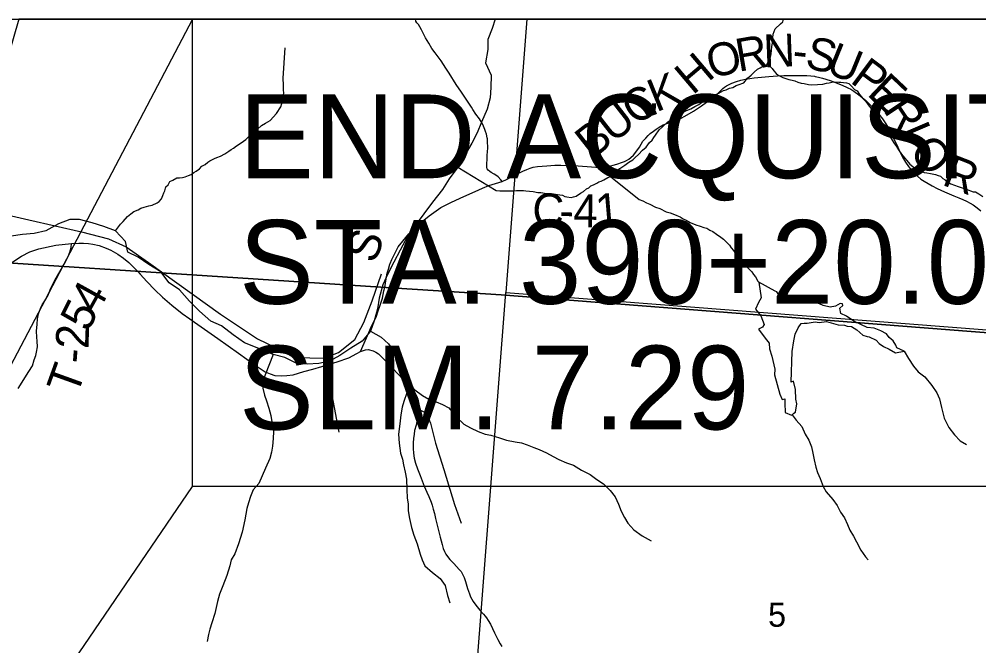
# Model space of a CAD drawing. Extents: x 0 to 34, y 0 to 22.
# Drawn here: x 6.769 to 8.431, y 19.816 to 20.9 of the extents above; entities that cross this region are included whole.
import ezdxf

# ---------------------------------------------------------------- set-up
doc = ezdxf.new("R2010")
doc.units = 0
for name, color, linetype in [('GM_X_County_Road', 7, 'Continuous'), ('GM_X_County_Road_Text', 7, 'Continuous'), ('GM_X_Minor_Lake', 7, 'Continuous'), ('GM_X_Minor_River', 7, 'Continuous'), ('GM_X_Rail_Line', 7, 'Continuous'), ('GM_X_Section', 7, 'Continuous'), ('GM_X_Section_Text', 7, 'Continuous'), ('GM_X_State_Route', 7, 'Continuous'), ('GM_X_Township_Road', 7, 'Continuous'), ('GM_X_Township_Road_Text', 7, 'Continuous'), ('GM_X_Unincorporated', 7, 'Continuous'), ('SH_Cut_Line', 7, 'Continuous'), ('SH_Data', 7, 'Continuous'), ('SH_Masking', 7, 'Continuous'), ('SH_Text', 7, 'Continuous')]:
    doc.layers.add(name, color=color, linetype=linetype)

msp = doc.modelspace()

# ---------------------------------------------------------------- linework, layer by layer
at = {"layer": 'GM_X_County_Road'}
for points in [[(7.5391, 20.593), (7.5586, 20.6019), (7.5715, 20.6074), (7.5825, 20.6121), (7.6053, 20.619), (7.614, 20.6232), (7.6228, 20.6278), (7.6294, 20.6313), (7.6364, 20.6349), (7.6412, 20.6372), (7.648, 20.64), (7.6537, 20.6422), (7.6589, 20.6436), (7.6664, 20.6448), (7.6828, 20.646), (7.6968, 20.6472), (7.7073, 20.6474), (7.7212, 20.6468), (7.7373, 20.6464), (7.76, 20.6443), (7.7677, 20.6436), (7.7731, 20.6435), (7.7789, 20.6437), (7.7848, 20.6442), (7.791, 20.6455), (7.7978, 20.6474), (7.8039, 20.6492), (7.8139, 20.6527), (7.8171, 20.6537), (7.8206, 20.6554), (7.8245, 20.6577), (7.8281, 20.6606), (7.8326, 20.6645), (7.837, 20.67), (7.8431, 20.6785), (7.8492, 20.6886), (7.8541, 20.6939), (7.8583, 20.6987), (7.8618, 20.7021), (7.8673, 20.7062), (7.8719, 20.7094), (7.8772, 20.713), (7.8841, 20.717), (7.8904, 20.7196), (7.9001, 20.7229), (7.9092, 20.7265), (7.9151, 20.7287), (7.9218, 20.732), (7.9365, 20.7407), (7.9504, 20.7498), (7.9594, 20.7563), (7.9684, 20.7632), (7.9798, 20.7728), (7.9876, 20.7802), (7.9903, 20.7821), (7.9939, 20.7845), (7.9984, 20.7869), (8.0032, 20.7893), (8.0109, 20.7922), (8.0188, 20.7946), (8.027, 20.7962), (8.0419, 20.7982), (8.067, 20.8008), (8.0821, 20.8021), (8.0929, 20.8024), (8.1077, 20.8027), (8.1206, 20.8027), (8.133, 20.8024), (8.1398, 20.802), (8.146, 20.8011), (8.1471, 20.8009)], [(8.1471, 20.8009), (8.1533, 20.7997), (8.1599, 20.7979), (8.1732, 20.7937), (8.1912, 20.7869), (8.2007, 20.783), (8.2041, 20.7813), (8.2091, 20.7787), (8.2143, 20.7752), (8.2227, 20.7691), (8.2342, 20.7599), (8.2375, 20.7567), (8.2443, 20.7503), (8.2516, 20.7428), (8.2577, 20.7355), (8.2639, 20.7275), (8.2698, 20.7189), (8.2746, 20.7104), (8.2788, 20.702), (8.2904, 20.6783), (8.2942, 20.6693), (8.2988, 20.661), (8.3039, 20.6528), (8.309, 20.645), (8.3108, 20.6426), (8.3148, 20.6381), (8.319, 20.6335), (8.3246, 20.6282), (8.3303, 20.6233), (8.3359, 20.6196), (8.3427, 20.6155), (8.3498, 20.6114), (8.3584, 20.6067), (8.3711, 20.6011), (8.3874, 20.5944), (8.3963, 20.5908), (8.403, 20.588), (8.4096, 20.5848), (8.4155, 20.5815), (8.4208, 20.5785), (8.4275, 20.5734), (8.434, 20.5683)], [(7.4112, 20.4762), (7.4115, 20.4771), (7.4145, 20.484), (7.4206, 20.4968), (7.4256, 20.5061), (7.4333, 20.5159), (7.4437, 20.5288), (7.4609, 20.5444), (7.4793, 20.5599), (7.4995, 20.574), (7.5179, 20.5832), (7.5391, 20.593)], [(7.3602, 20.3247), (7.3746, 20.3578), (7.3795, 20.3686), (7.3874, 20.3845), (7.3908, 20.395), (7.3944, 20.405), (7.3981, 20.417), (7.4007, 20.4296), (7.4021, 20.4354), (7.4048, 20.4505), (7.4066, 20.4604), (7.4085, 20.4673), (7.4112, 20.4762)]]:
    msp.add_lwpolyline(points, dxfattribs=at)
at = {"layer": 'GM_X_Minor_Lake'}
for points in [[(8.0496, 20.4448), (8.0539, 20.418), (8.049, 20.4097), (8.0443, 20.3983), (8.0534, 20.3865), (8.0589, 20.3717), (8.0562, 20.3668), (8.0494, 20.3638), (8.0607, 20.3477), (8.0678, 20.3394), (8.0681, 20.3295), (8.0726, 20.3169), (8.0773, 20.2941), (8.0769, 20.2843), (8.0861, 20.2512), (8.0902, 20.2417), (8.0948, 20.2432), (8.0951, 20.2356), (8.0954, 20.2192), (8.1063, 20.2146), (8.1078, 20.2154), (8.1105, 20.218), (8.1132, 20.2199), (8.1156, 20.2343), (8.1137, 20.2423), (8.1131, 20.259), (8.1101, 20.2734), (8.1056, 20.2719), (8.1075, 20.325), (8.1106, 20.3436), (8.1126, 20.3546), (8.118, 20.3659), (8.1229, 20.3731), (8.1283, 20.3742), (8.1336, 20.3742), (8.1476, 20.376), (8.1544, 20.3752), (8.1669, 20.3766), (8.1873, 20.3708), (8.1983, 20.3707), (8.2028, 20.3688), (8.21, 20.368), (8.2194, 20.3626), (8.2296, 20.353), (8.2375, 20.3507), (8.241, 20.3503), (8.253, 20.3445), (8.2583, 20.3388), (8.2655, 20.3334), (8.2756, 20.3288), (8.2862, 20.3227)], [(8.3014, 20.3254), (8.2885, 20.3314), (8.2867, 20.336), (8.2822, 20.3432), (8.2754, 20.3493), (8.2709, 20.3554), (8.2611, 20.3608), (8.2494, 20.3654), (8.2373, 20.3667), (8.2142, 20.3774), (8.2014, 20.3859), (8.192, 20.3909), (8.1902, 20.4), (8.1951, 20.4045), (8.1948, 20.4075), (8.1906, 20.408), (8.1826, 20.4031), (8.1735, 20.4016), (8.161, 20.4047), (8.1546, 20.4074), (8.1425, 20.4117), (8.1236, 20.4156), (8.1115, 20.4168), (8.1001, 20.4154), (8.0933, 20.4158), (8.0862, 20.4204), (8.0809, 20.4281), (8.0783, 20.4292), (8.0496, 20.4448)], [(8.2862, 20.3227), (8.3014, 20.3254)]]:
    msp.add_lwpolyline(points, dxfattribs=at)
at = {"layer": 'GM_X_Minor_River'}
for points in [[(7.5936, 20.9), (7.5882, 20.8841), (7.5809, 20.8648), (7.5808, 20.8477), (7.5765, 20.8246), (7.5866, 20.8032), (7.5856, 20.782), (7.5848, 20.7641), (7.5793, 20.7444), (7.5697, 20.722), (7.5624, 20.7035), (7.5531, 20.6857), (7.5393, 20.6618), (7.5286, 20.6436), (7.5137, 20.6236), (7.5022, 20.6054), (7.485, 20.5835), (7.4547, 20.543), (7.4421, 20.5248), (7.4287, 20.5002), (7.4179, 20.4794), (7.4071, 20.4582), (7.3991, 20.44), (7.3925, 20.4172), (7.3897, 20.399), (7.3839, 20.3781), (7.3773, 20.3603), (7.3631, 20.3425), (7.3437, 20.3309), (7.3247, 20.3181), (7.3064, 20.3083), (7.2882, 20.3042), (7.2681, 20.3028), (7.248, 20.3052), (7.2291, 20.3144), (7.209, 20.3198), (7.1844, 20.3302), (7.1595, 20.3398), (7.1399, 20.354), (7.1195, 20.3693), (7.1009, 20.3773), (7.0813, 20.3945), (7.064, 20.4121), (7.0467, 20.4315), (7.029, 20.4438), (7.0147, 20.4628), (6.9939, 20.4755), (6.9754, 20.4881), (6.9573, 20.4969), (6.9536, 20.5152), (6.9363, 20.5339), (6.9162, 20.5412), (6.8958, 20.5474), (6.8738, 20.5536), (6.8568, 20.5533), (6.8374, 20.5458), (6.8153, 20.5338), (6.7952, 20.5289), (6.7751, 20.5275), (6.7557, 20.5246)], [(8.059, 20.8177), (8.0629, 20.8203), (8.066, 20.8256), (8.069, 20.8294), (8.0706, 20.8366), (8.0714, 20.8403), (8.0719, 20.8457), (8.0723, 20.8529), (8.0732, 20.8582), (8.074, 20.8677), (8.0749, 20.8741), (8.078, 20.8832), (8.0872, 20.8918), (8.0914, 20.8952), (8.0924, 20.9)], [(6.9363, 20.5339), (6.9447, 20.5452), (6.9493, 20.5497), (6.957, 20.5587), (6.9627, 20.5629), (6.9681, 20.5673), (6.9753, 20.5703), (6.9799, 20.5729), (6.986, 20.5747), (6.994, 20.5769), (6.9997, 20.5783), (7.0081, 20.5824), (7.0119, 20.5847), (7.0158, 20.5892), (7.0181, 20.5948), (7.02, 20.5994), (7.0216, 20.6032), (7.0232, 20.6096), (7.027, 20.6133), (7.0301, 20.619), (7.0351, 20.6216), (7.042, 20.6253), (7.0469, 20.6256), (7.0522, 20.626), (7.0568, 20.627), (7.0625, 20.6292), (7.0671, 20.6311), (7.072, 20.6348), (7.0759, 20.6371), (7.0816, 20.6408), (7.0858, 20.6457), (7.0912, 20.6483), (7.0958, 20.6524), (7.0996, 20.6546), (7.1076, 20.6591), (7.1118, 20.6605), (7.1179, 20.6627), (7.1255, 20.6672), (7.1324, 20.6713), (7.1366, 20.6743), (7.1404, 20.6765), (7.1454, 20.6806), (7.1534, 20.6859), (7.1577, 20.6888), (7.1615, 20.6918), (7.1669, 20.6971), (7.1711, 20.7008), (7.1772, 20.7072), (7.1818, 20.7098), (7.1887, 20.7162), (7.1956, 20.7203), (7.2036, 20.7244), (7.2151, 20.7368), (7.2221, 20.7481), (7.224, 20.7541), (7.2256, 20.7606), (7.2269, 20.7682), (7.2273, 20.7723), (7.227, 20.7769), (7.227, 20.7822), (7.2267, 20.786), (7.2264, 20.7978), (7.2301, 20.8502)], [(7.5286, 20.6436), (7.5949, 20.6035), (7.6013, 20.6027), (7.6051, 20.603), (7.6165, 20.6029), (7.6244, 20.6031), (7.6301, 20.6034), (7.6427, 20.6033), (7.6464, 20.6029), (7.6529, 20.6024), (7.6593, 20.6016), (7.6673, 20.6003), (7.6722, 20.5999), (7.6821, 20.5982), (7.6877, 20.5978), (7.6915, 20.5977), (7.6976, 20.5969), (7.7056, 20.596), (7.7097, 20.5952), (7.7139, 20.5933), (7.7177, 20.5925), (7.7248, 20.5912), (7.7287, 20.5923), (7.7336, 20.5938), (7.7412, 20.599), (7.7462, 20.602), (7.7516, 20.6065), (7.7554, 20.6083), (7.7592, 20.6117), (7.7638, 20.6135), (7.7691, 20.6161), (7.773, 20.6184), (7.7771, 20.6195), (7.7814, 20.6221), (7.7886, 20.6258), (7.7932, 20.6276), (7.7978, 20.631), (7.8016, 20.6343), (7.8054, 20.637), (7.8093, 20.6415), (7.8181, 20.6474), (7.8249, 20.6523), (7.8315, 20.6568), (7.836, 20.6605), (7.8414, 20.6658), (7.8487, 20.6733), (7.8545, 20.6785), (7.8606, 20.6868), (7.8652, 20.6906), (7.8679, 20.6955), (7.871, 20.6992), (7.8772, 20.7086), (7.8826, 20.7131), (7.8922, 20.7225), (7.8967, 20.7251), (7.9036, 20.7311), (7.9097, 20.7337), (7.9143, 20.7359), (7.9216, 20.7408), (7.9322, 20.7448), (7.9391, 20.7489), (7.946, 20.7522), (7.9544, 20.7586), (7.9586, 20.7604), (7.9647, 20.7649), (7.9685, 20.766), (7.9731, 20.7686), (7.9796, 20.7716), (7.9888, 20.7764), (7.9933, 20.7779), (7.999, 20.7805), (8.0048, 20.7819), (8.0105, 20.7852), (8.0143, 20.7863), (8.0238, 20.79), (8.0304, 20.7979), (8.0365, 20.8032), (8.0419, 20.8084), (8.0476, 20.8133), (8.0522, 20.8159), (8.0591, 20.8196), (8.0629, 20.8207), (8.0678, 20.8199), (8.073, 20.8149), (8.076, 20.8106)], [(8.076, 20.8106), (8.0798, 20.8057), (8.0835, 20.8029), (8.0915, 20.799), (8.1017, 20.7955), (8.1073, 20.7943), (8.1119, 20.7931), (8.1172, 20.7911), (8.1232, 20.7895), (8.1285, 20.7887), (8.1357, 20.7871), (8.141, 20.7866), (8.1516, 20.7869), (8.1607, 20.7875), (8.1672, 20.789), (8.1714, 20.7897), (8.176, 20.7908), (8.1813, 20.7915), (8.1881, 20.791), (8.1919, 20.7909), (8.1961, 20.7905), (8.2017, 20.7901), (8.2055, 20.7889), (8.2104, 20.7842), (8.2157, 20.7785), (8.2198, 20.7758), (8.2239, 20.7696), (8.2306, 20.7623), (8.2351, 20.7577), (8.2411, 20.7496), (8.2482, 20.7408), (8.2523, 20.7366), (8.2553, 20.7324), (8.2591, 20.7266), (8.2647, 20.7182), (8.2684, 20.7147), (8.271, 20.7094), (8.2743, 20.7029), (8.278, 20.6952), (8.2836, 20.686), (8.2881, 20.6795), (8.2915, 20.6738), (8.2967, 20.6665), (8.3019, 20.6603), (8.306, 20.6553), (8.3113, 20.6492), (8.3192, 20.6426), (8.3267, 20.6383), (8.3305, 20.6372), (8.3358, 20.6344), (8.3407, 20.634), (8.3471, 20.6328), (8.3558, 20.6311), (8.3604, 20.6296), (8.3642, 20.6284), (8.3683, 20.6241), (8.3724, 20.6218), (8.3766, 20.6183), (8.3822, 20.6148), (8.3886, 20.6125), (8.3951, 20.6105), (8.4034, 20.6074), (8.4075, 20.6065), (8.4162, 20.603), (8.4211, 20.6014), (8.4249, 20.601), (8.4306, 20.5979), (8.4377, 20.5932)], [(7.7932, 20.6276), (7.8428, 20.5882), (7.8492, 20.5859), (7.8556, 20.5824), (7.8613, 20.5796), (7.8711, 20.5746), (7.8787, 20.5722), (7.8896, 20.5667), (7.8964, 20.5647), (7.9036, 20.562), (7.9081, 20.56), (7.9134, 20.5577), (7.9187, 20.5542), (7.9239, 20.5519), (7.9307, 20.548), (7.9406, 20.544), (7.9481, 20.5417), (7.9545, 20.5397), (7.9598, 20.5381), (7.9651, 20.535), (7.97, 20.5326), (7.9768, 20.528), (7.9843, 20.523), (7.9884, 20.5191), (7.9945, 20.5137), (7.999, 20.5091), (8.0019, 20.5045), (8.0057, 20.4995), (8.0102, 20.4934), (8.0128, 20.4888), (8.018, 20.4826), (8.0229, 20.478), (8.0259, 20.4742), (8.0296, 20.4711), (8.033, 20.4672), (8.0375, 20.4626), (8.0405, 20.4584), (8.0438, 20.4542), (8.0479, 20.4465), (8.0496, 20.4448)], [(7.3773, 20.3603), (7.396, 20.3497), (7.409, 20.3379), (7.4158, 20.3284), (7.4203, 20.3158), (7.4249, 20.3052), (7.4298, 20.2953), (7.4378, 20.2816), (7.4454, 20.2683), (7.4541, 20.2588), (7.4678, 20.2489), (7.4788, 20.2424), (7.4914, 20.2375), (7.502, 20.2333), (7.513, 20.2272), (7.5256, 20.212), (7.5392, 20.199), (7.5506, 20.1925), (7.5639, 20.1865), (7.5761, 20.1819), (7.586, 20.18), (7.6008, 20.1754), (7.6129, 20.1716), (7.6281, 20.1685), (7.6388, 20.167), (7.649, 20.1632), (7.6601, 20.1586), (7.6696, 20.1552), (7.6821, 20.1495), (7.6939, 20.1434), (7.7034, 20.1381), (7.7171, 20.132), (7.7288, 20.1282), (7.7429, 20.1194), (7.7577, 20.1122), (7.7695, 20.1034), (7.7809, 20.0958), (7.7923, 20.0844), (7.801, 20.0734), (7.8071, 20.0608), (7.8116, 20.0486), (7.817, 20.0376), (7.823, 20.0277), (7.8337, 20.0163), (7.8481, 20.0057), (7.8633, 19.9973)], [(7.209, 20.3198), (7.1953, 20.2844), (7.1907, 20.2719), (7.1911, 20.2616), (7.1941, 20.2491), (7.1976, 20.2396), (7.2017, 20.2266), (7.2048, 20.2141), (7.2074, 20.1996), (7.2097, 20.1863), (7.2089, 20.1742), (7.2081, 20.1609), (7.2062, 20.1506), (7.2032, 20.1396), (7.196, 20.1229), (7.1842, 20.0966), (7.1743, 20.0856), (7.1701, 20.0742), (7.1663, 20.0628), (7.1636, 20.0529), (7.1617, 20.0434), (7.1602, 20.0335), (7.1552, 20.0123), (7.1491, 19.9921), (7.1426, 19.975), (7.1366, 19.9644), (7.1339, 19.9541), (7.1286, 19.937), (7.1221, 19.9195), (7.1164, 19.9047), (7.1129, 19.8925), (7.108, 19.8716), (7.103, 19.8553), (7.0992, 19.8446), (7.0973, 19.8351), (7.095, 19.823)], [(8.3014, 20.3254), (8.309, 20.3125), (8.3173, 20.2996), (8.3257, 20.2897), (8.3371, 20.2813), (8.3492, 20.2661), (8.358, 20.2531), (8.3625, 20.2429), (8.3663, 20.228), (8.3709, 20.2098), (8.3788, 20.1931), (8.3883, 20.1809), (8.3986, 20.1702), (8.4096, 20.1641)], [(7.4454, 20.2683), (7.4454, 20.2683), (7.4351, 20.2386), (7.4324, 20.2288), (7.4302, 20.2154), (7.4286, 20.1999), (7.4259, 20.182), (7.4271, 20.1664), (7.4297, 20.1489), (7.4331, 20.1386), (7.4347, 20.1288), (7.4377, 20.1158), (7.4396, 20.1037), (7.4403, 20.0862), (7.4411, 20.0713), (7.4426, 20.0611), (7.443, 20.0493), (7.4452, 20.0356), (7.4486, 20.0204), (7.4528, 20.0071), (7.4581, 19.9919), (7.4634, 19.9744), (7.4668, 19.9641), (7.4718, 19.9542), (7.4851, 19.9424), (7.498, 19.9322), (7.5067, 19.92), (7.5109, 19.9029), (7.5147, 19.8899)], [(8.1078, 20.2154), (8.1142, 20.2058), (8.124, 20.1951), (8.1303, 20.1818), (8.1363, 20.1715), (8.1408, 20.1597), (8.1434, 20.1487), (8.1456, 20.1373), (8.1485, 20.1248), (8.1515, 20.1153), (8.1559, 20.105), (8.1612, 20.0913), (8.1664, 20.0818), (8.1777, 20.0688), (8.1855, 20.0585), (8.1911, 20.0471), (8.1979, 20.0368), (8.2035, 20.0257), (8.2076, 20.0155), (8.2136, 20.0052), (8.2188, 19.9953), (8.2263, 19.9808), (8.2342, 19.9698), (8.2391, 19.9644)]]:
    msp.add_lwpolyline(points, dxfattribs=at)
at = {"layer": 'GM_X_Rail_Line'}
msp.add_lwpolyline([(6.6755, 20.58), (6.7104, 20.5699), (6.786, 20.5529), (6.8773, 20.532), (6.9242, 20.5201), (6.9546, 20.5061), (6.9935, 20.4787), (7.1181, 20.3894), (7.1819, 20.3468), (7.2278, 20.3247), (7.2611, 20.3146), (7.2724, 20.3137), (7.2967, 20.3131), (7.3223, 20.323), (7.3505, 20.3456), (7.3658, 20.3753), (7.3804, 20.4123), (7.3964, 20.4594)], dxfattribs=at)
at = {"layer": 'GM_X_Section'}
msp.add_lwpolyline([(7.6117, 20.4271), (8.6303, 20.3481), (8.5509, 19.3356), (7.5335, 19.4104)], close=True, dxfattribs=at)
at = {"layer": 'GM_X_State_Route'}
for points in [[(6.709, 20.4391), (6.7464, 20.4708), (6.7546, 20.4773), (6.7616, 20.4825), (6.7733, 20.4901), (6.788, 20.4973), (6.8034, 20.5027), (6.8327, 20.5088), (6.8601, 20.512)], [(6.8601, 20.512), (6.8728, 20.5122), (6.8807, 20.5121), (6.8891, 20.5117), (6.8968, 20.5107), (6.9076, 20.5081), (6.9199, 20.5036), (6.928, 20.5001), (6.9404, 20.4933), (6.9498, 20.4866), (6.959, 20.4787), (6.9747, 20.4631), (6.9789, 20.4585), (6.9902, 20.4463), (7.0041, 20.4318), (7.0176, 20.4187), (7.0335, 20.4051), (7.0518, 20.3909), (7.0647, 20.3817), (7.0731, 20.3759), (7.1135, 20.3473), (7.1492, 20.3219), (7.1637, 20.3114), (7.1813, 20.2987), (7.1953, 20.2895), (7.204, 20.2861), (7.2119, 20.2836), (7.223, 20.2825), (7.2329, 20.2831), (7.2434, 20.2847), (7.2619, 20.2901), (7.2777, 20.2945), (7.2935, 20.299), (7.3006, 20.3015), (7.32, 20.3069), (7.3401, 20.3141), (7.3539, 20.3215), (7.3602, 20.3247), (7.3687, 20.3278), (7.3738, 20.3282), (7.3823, 20.3259), (7.3866, 20.3238), (7.3915, 20.321), (7.4066, 20.3061), (7.4345, 20.2761), (7.4496, 20.2599), (7.4545, 20.2536), (7.4576, 20.247), (7.4594, 20.2424), (7.4609, 20.2368), (7.4617, 20.2308), (7.4619, 20.2246), (7.4612, 20.2191), (7.4599, 20.2124), (7.4579, 20.2035), (7.4565, 20.1973), (7.454, 20.1881), (7.4532, 20.1821), (7.4518, 20.1741), (7.4514, 20.1669), (7.4514, 20.1573), (7.4521, 20.1491), (7.4532, 20.1404), (7.4555, 20.1318), (7.4589, 20.1216), (7.4633, 20.1102), (7.4705, 20.0921), (7.4752, 20.0814), (7.4784, 20.0741), (7.4823, 20.0644), (7.4841, 20.059), (7.4863, 20.0523), (7.4883, 20.0443), (7.4903, 20.0361), (7.498, 20.0037), (7.5015, 19.9909), (7.5036, 19.984), (7.5058, 19.9789), (7.5082, 19.9743), (7.5111, 19.9699), (7.5147, 19.9652), (7.5216, 19.9578), (7.5267, 19.9527), (7.5313, 19.9479), (7.5344, 19.944), (7.5368, 19.9398), (7.5395, 19.934), (7.542, 19.9267), (7.5456, 19.9146), (7.5489, 19.9054), (7.5509, 19.9006), (7.5554, 19.8922), (7.5599, 19.8859), (7.567, 19.8774), (7.5733, 19.8703), (7.5762, 19.867), (7.5783, 19.8637), (7.5812, 19.8596), (7.5851, 19.8532), (7.5922, 19.8381), (7.5978, 19.8262), (7.6018, 19.8191), (7.6049, 19.8146)]]:
    msp.add_lwpolyline(points, dxfattribs=at)
at = {"layer": 'GM_X_Township_Road'}
msp.add_line((7.3006, 20.3015), (7.3228, 20.185), dxfattribs=at)
for points in [[(7.6053, 20.619), (7.603, 20.622), (7.5983, 20.6272), (7.5946, 20.6299), (7.5915, 20.6317), (7.5867, 20.6346), (7.5843, 20.6361), (7.5813, 20.6388), (7.5796, 20.6412), (7.5789, 20.6433), (7.5789, 20.6451), (7.579, 20.6495), (7.5794, 20.6579), (7.5798, 20.6638), (7.5801, 20.6709), (7.5804, 20.6768), (7.5806, 20.6808), (7.5803, 20.6852), (7.5799, 20.6932), (7.5796, 20.6949), (7.5781, 20.7009), (7.5769, 20.7054), (7.5756, 20.7092), (7.5731, 20.715), (7.5709, 20.72), (7.5661, 20.7274), (7.56, 20.7358), (7.5549, 20.7436), (7.5525, 20.7475), (7.5349, 20.7738), (7.526, 20.7872), (7.5137, 20.8065), (7.5082, 20.8154), (7.4996, 20.8279), (7.4897, 20.8415), (7.4895, 20.8418), (7.4839, 20.8495), (7.4785, 20.8582), (7.473, 20.8676), (7.466, 20.8816), (7.4631, 20.8868), (7.4604, 20.8907), (7.4579, 20.8935), (7.4562, 20.8968), (7.4552, 20.9)], [(6.7862, 20.2901), (6.7924, 20.3), (6.7952, 20.3103), (6.798, 20.3178), (6.7995, 20.3236), (6.8009, 20.3329), (6.8003, 20.3429), (6.8002, 20.3499), (6.7996, 20.3603), (6.8003, 20.3724), (6.8009, 20.3815), (6.8029, 20.3901), (6.8061, 20.3991), (6.8091, 20.4059), (6.8136, 20.4128), (6.8197, 20.4226), (6.8232, 20.4315), (6.8267, 20.4389), (6.8335, 20.4522), (6.8444, 20.4715), (6.8492, 20.4787), (6.8544, 20.4895), (6.8571, 20.497), (6.8591, 20.5047), (6.8601, 20.512)], [(6.7676, 20.2606), (6.7862, 20.2901)], [(7.4619, 20.2246), (7.4699, 20.2207), (7.4765, 20.2131), (7.4812, 20.201), (7.4901, 20.1665), (7.5046, 20.1206), (7.5228, 20.06), (7.5347, 20.0276)]]:
    msp.add_lwpolyline(points, dxfattribs=at)
at = {"layer": 'GM_X_Township_Road_Text'}
msp.add_lwpolyline([(8.673, 20.9), (7.6479, 20.9), (7.6117, 20.4271), (8.6303, 20.3481)], close=True, dxfattribs=at)
at = {"layer": 'GM_X_Unincorporated'}
msp.add_lwpolyline([(8.9, 20.3234), (8.9, 20.9), (6.769, 20.9), (6.6568, 20.5136), (6.6484, 20.4847), (6.6718, 20.4832), (6.7584, 20.4776), (6.8381, 20.4724), (6.962, 20.4644), (7.3955, 20.4364), (7.6038, 20.4229), (8.6245, 20.3436)], close=True, dxfattribs=at)
msp.add_lwpolyline([(8.9, 14.2264), (8.9, 20.3234), (8.6245, 20.3436), (7.6038, 20.4229), (7.3955, 20.4364), (6.962, 20.4644), (6.8381, 20.4724), (6.7584, 20.4776), (6.6718, 20.4832), (6.6484, 20.4847), (4.3099, 20.6409), (3.8602, 20.6728), (3.5651, 20.6937), (3.5462, 20.4144), (3.5457, 20.4056), (3.5456, 20.4047), (3.5099, 19.8769)], dxfattribs=at)
at = {"layer": 'SH_Cut_Line'}
msp.add_lwpolyline([(8.9, 14.1), (8.9, 20.9), (6.769, 20.9), (6.6568, 20.5136), (6.6484, 20.4847), (4.3099, 20.6409), (3.8602, 20.6728), (3.5651, 20.6937), (3.5462, 20.4144), (3.5457, 20.4056), (3.5456, 20.4047), (3.5099, 19.8769), (3.4599, 19.1361), (3.4595, 19.1305), (3.4011, 18.2653), (3.709, 17.484), (3.7367, 17.4136), (3.972, 16.8916), (4.0882, 16.6114), (4.2937, 16.1161)], dxfattribs=at)
at = {"layer": 'SH_Data'}
msp.add_line((2.1, 20.9), (8.9, 20.9), dxfattribs=at)
at = {"layer": 'SH_Masking'}
msp.add_lwpolyline([(7.0694, 20.9), (8.9, 20.9), (8.9, 20.091), (7.0694, 20.091)], close=True, dxfattribs=at)
at = {"layer": 'SH_Text'}
msp.add_lwpolyline([(7.0694, 20.091), (7.0694, 20.9), (5.2191, 17.3772)], close=True, dxfattribs=at)

# ---------------------------------------------------------------- texts
at = {"layer": 'GM_X_County_Road_Text'}
for s, rotation, p in [('R', 9.649, (8.0146, 20.8089)), ('N', 2.1333, (8.0586, 20.8165)), ('S', 347.371, (8.128, 20.8162)), ('O', 14.387, (7.9674, 20.7967)), ('U', 337.8363, (8.163, 20.8086)), ('H', 40.2209, (7.9352, 20.7675)), ('-', 353.943, (8.1064, 20.8184)), ('P', 323.2717, (8.206, 20.7916)), ('K', 22.1883, (7.8722, 20.7385)), ('E', 316.532, (8.2353, 20.7698)), ('C', 33.0985, (7.8357, 20.7144)), ('R', 303.3956, (8.264, 20.7432)), ('U', 38.0568, (7.7973, 20.6843)), ('B', 38.2048, (7.7607, 20.6555)), ('I', 293.1699, (8.2884, 20.7066)), ('O', 311.0948, (8.3079, 20.6688)), ('R', 338.6875, (8.3649, 20.6141)), ('C', 357.972, (7.6568, 20.5426)), ('4', 359.4902, (7.7284, 20.5402)), ('1', 4.7978, (7.7692, 20.5401)), ('-', 358.2814, (7.7038, 20.5409)), ('S', 68.9918, (7.3847, 20.4752))]:
    msp.add_text(s, height=0.0568, rotation=rotation, dxfattribs=at).set_placement(p)
at = {"layer": 'GM_X_Section_Text'}
msp.add_text('5', height=0.0419, rotation=0, dxfattribs=at).set_placement((8.0658, 19.8485))
at = {"layer": 'GM_X_Township_Road_Text'}
for s, rotation, p in [('4', 61.0523, (6.9042, 20.3882)), ('5', 63.4396, (6.8888, 20.3575)), ('2', 87.977, (6.8892, 20.3287)), ('-', 85.7957, (6.8873, 20.3031)), ('T', 70.1805, (6.8694, 20.2466))]:
    msp.add_text(s, height=0.0568, rotation=rotation, dxfattribs=at).set_placement(p)
at = {"layer": 'SH_Text'}
for s, height, p in [('END ACQUISITION', 0.144931, (7.15, 20.6248)), ('STA. 390+20.00', 0.144931, (7.15, 20.4074)), ('SLM. 7.29', 0.14493, (7.15, 20.19))]:
    msp.add_text(s, height=height, rotation=360, dxfattribs=at).set_placement(p)

doc.saveas('drawing.dxf')
